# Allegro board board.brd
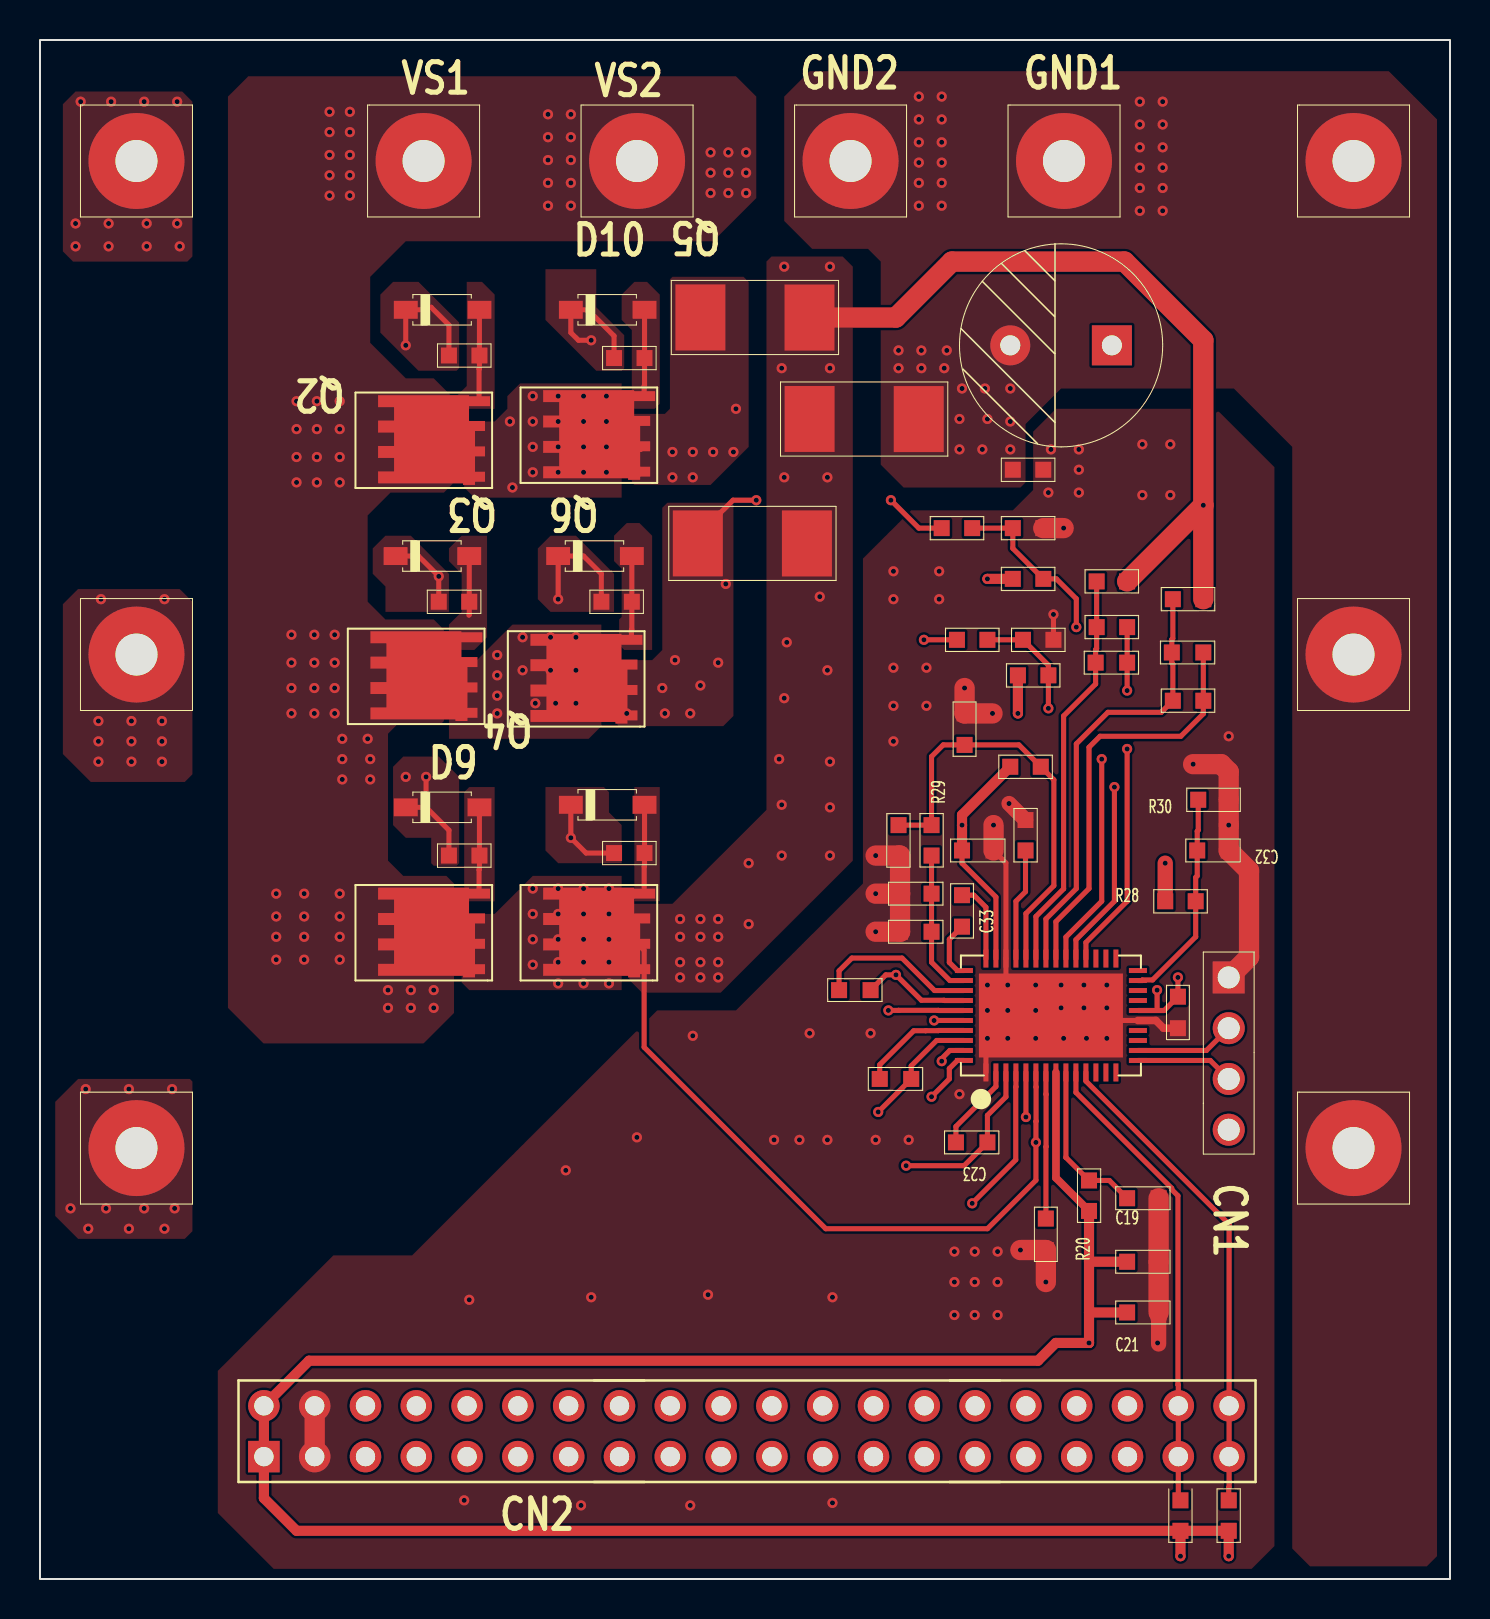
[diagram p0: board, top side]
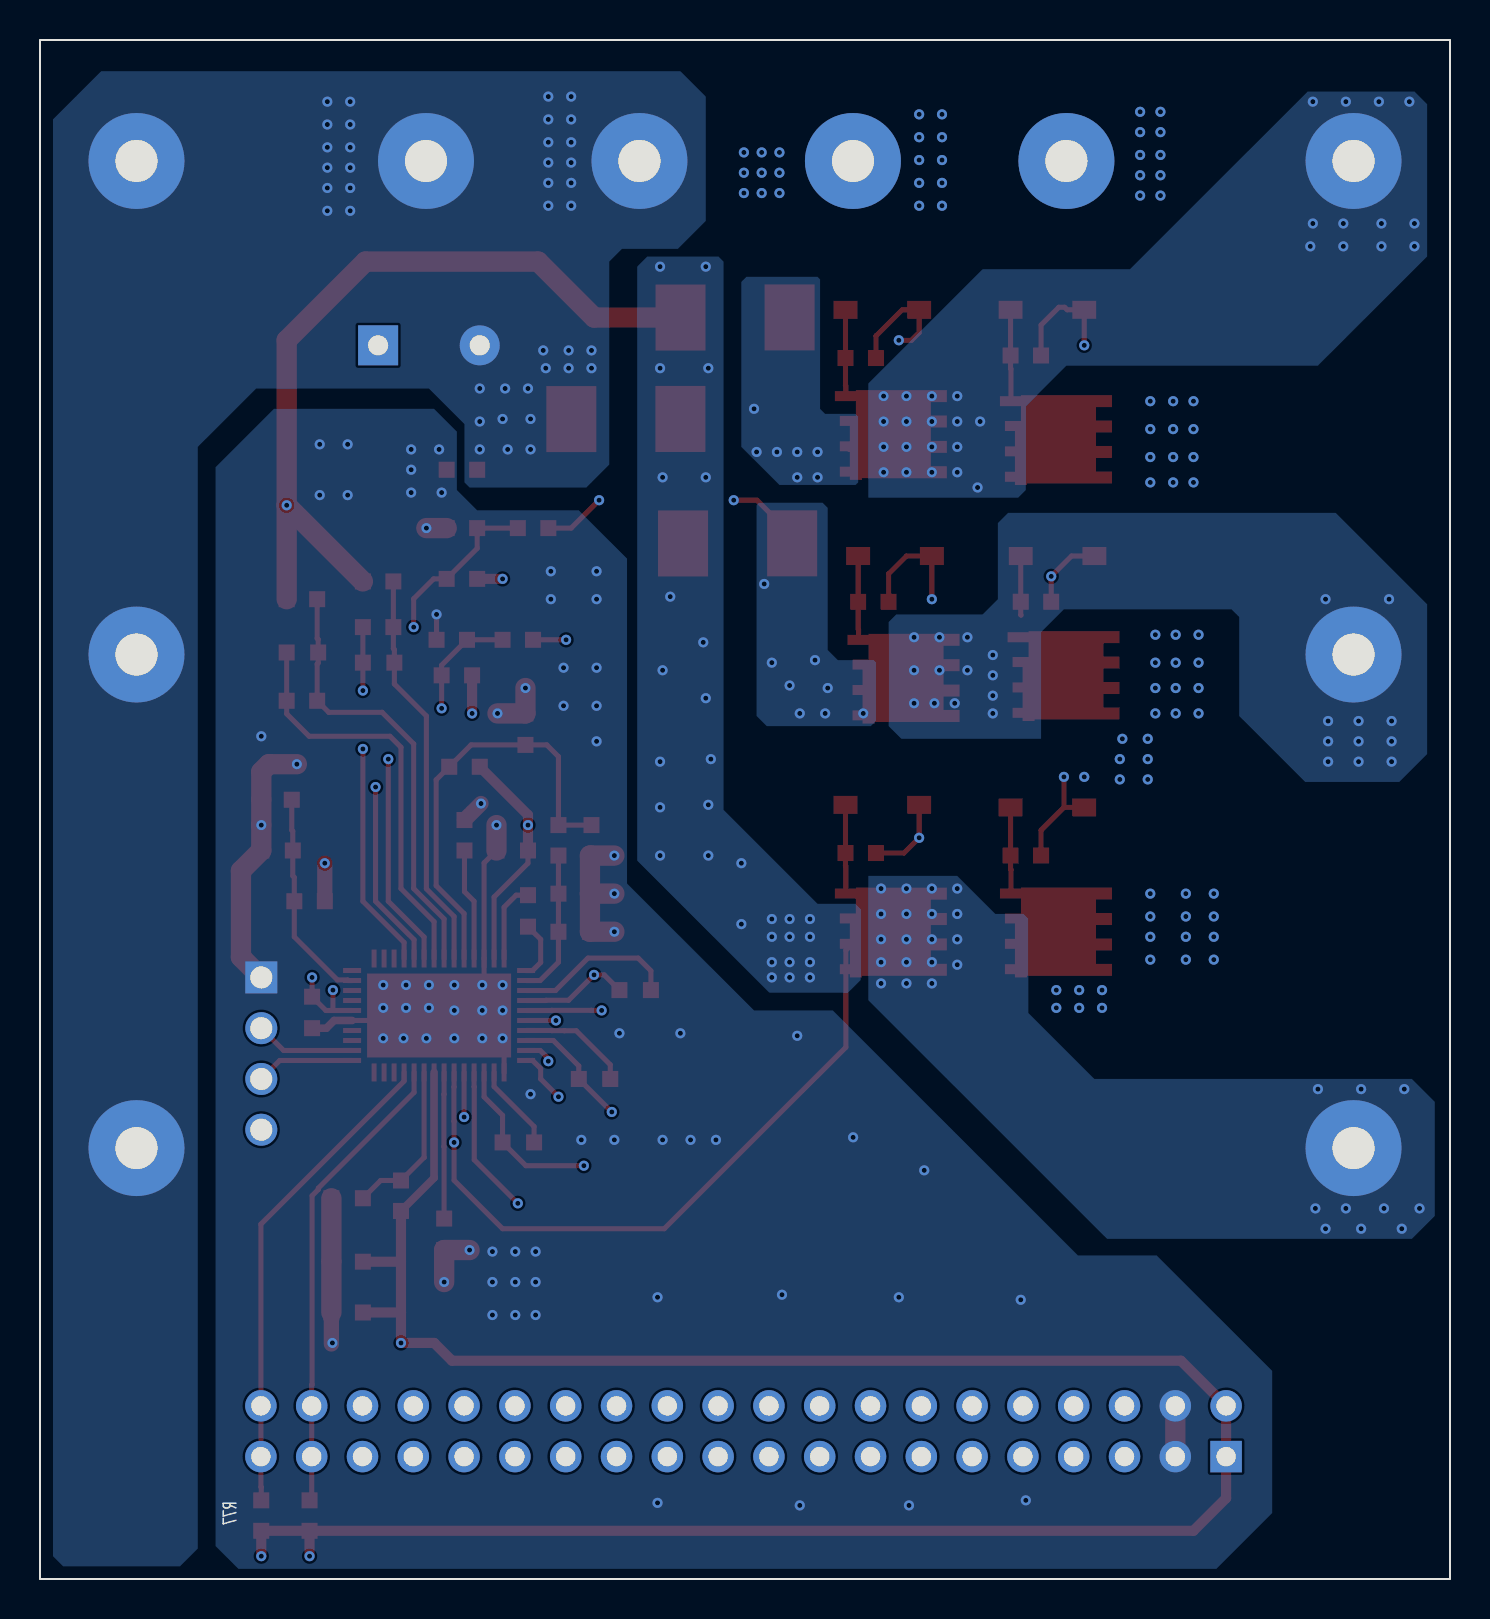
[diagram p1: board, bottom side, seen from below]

Outline 70.5 x 77 mm; copper layers: TOP, LAYER1, LAYER2, BOTTOM. Coordinates in mm from the lower left corner of the outline.
Outline path: rectangle 0,0 70.5,77

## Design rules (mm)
constraint set DEFAULT: min track width 0.127
net group N03788: nets N03788 N03879
net group N03886: nets N03886 N04171
net group IU: nets N05859 N05869 OP1- OP1O OP2- OP2O
net group OUT1: nets N03454
net group OUT2: nets N03434
net group OUT3: nets N03083

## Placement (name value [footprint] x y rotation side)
C19  0.1uF  [C0603]  54.36 19.05 0 top
C20  0.1uF  [C0603]  54.36 15.88 0 top
C21  10uF  [C0603]  54.36 13.34 0 top
C22  1uF  [C0603]  50.29 18.03 270 top
C23  0.47uF  [C0603]  47.37 21.84 180 top
C25  0.1uF  [C0603]  56.9 27.56 90 top
C30  0.47uF  [C0603]  43.56 25.02 180 top
C31  0.47uF  [C0603]  41.53 29.46 180 top
C32  0.1uF  [C0603]  59.44 36.45 180 top
C33  0.47uF  [C0603]  46.1 32.64 90 top
C34  10uF  [C0603]  44.58 32.38 180 top
C35  0.1uF  [C0603]  44.58 34.29 180 top
C36  0.1uF  [C0603]  46.1 36.45 0 top
C38  0.47uF  [C0603]  46.23 43.31 270 top
C45  0.01uF  [C0603]  54.36 45.85 180 top
C47  0.01uF  [C0603]  58.17 46.35 180 top
C48  330uF/35V  [CAP_ELECT_DIP_OD10_P5]  53.59 61.72 180 top
CN1  17.0017_4PIN_2.54mm  [CONN_DIP_4PIN_2_54MM]  59.44 30.1 270 top
CN2  17.0163_2X20_90D_female  [CONN_DIP_2X20PIN_2_54MM]  11.19 6.12 0 top
D7  200V;0.2A  [DIODES_SOD_123]  21.97 63.5 0 top
D8  200V;0.2A  [DIODES_SOD_123]  21.46 51.18 0 top
D9  200V;0.2A  [DIODES_SOD_123]  21.97 38.61 0 top
D10  200V;0.2A  [DIODES_SOD_123]  30.23 63.5 0 top
D11  200V;0.2A  [DIODES_SOD_123]  29.59 51.18 0 top
D12  200V;0.2A  [DIODES_SOD_123]  30.23 38.73 0 top
GND1  2.0mm_Male  [CONN_2_1MM_5_6MM]  51.2 70.95 0 top
GND2  2.0mm_Male  [CONN_2_1MM_5_6MM]  40.53 70.95 0 top
Q2  100V;90A  [MOS_TDSON8]  19.18 57.02 180 top
Q3  100V;90A  [MOS_TDSON8]  18.8 45.21 180 top
Q4  100V;90A  [MOS_TDSON8]  19.18 32.38 180 top
Q5  100V;90A  [MOS_TDSON8]  27.43 57.28 180 top
Q6  100V;90A  [MOS_TDSON8]  26.8 45.09 180 top
Q7  100V;90A  [MOS_TDSON8]  27.43 32.38 180 top
R20  10k  [R0603]  52.45 18.41 90 top
R28  120k  [R0603]  56.26 33.91 0 top
R29  100k  [R0603]  44.58 36.2 90 top
R30  10k  [R0603]  57.91 38.99 0 top
R31  15k  [R0603]  49.28 36.45 90 top
R33  NC  [R0603]  48.51 40.64 0 top
R36  NC  [R0603]  42.93 37.72 270 top
R43  47k  [R0603]  48.9 45.21 0 top
R44  47k  [R0603]  49.15 46.99 0 top
R45  1k  [R0603]  45.85 46.99 0 top
R47  1k  [R0603]  54.36 49.91 180 top
R51  51  [R0603]  20.45 61.21 0 top
R52  51  [R0603]  19.94 48.9 0 top
R53  51  [R0603]  20.45 36.2 0 top
R54  24k  [R0603]  54.36 47.62 180 top
R55  51  [R0603]  28.7 61.09 0 top
R56  51  [R0603]  28.07 48.9 0 top
R57  51  [R0603]  28.7 36.32 0 top
R58  47k  [R0603]  48.64 50.04 0 top
R59  47k  [R0603]  48.64 52.58 0 top
R60  0.002  [R2512]  33.02 63.12 0 top
R61  0.002  [R2512]  32.89 51.82 0 top
R62  1k  [R0603]  45.09 52.58 0 top
R64  1k  [R0603]  58.17 49.02 180 top
R65  0.005  [R2512]  38.48 58.04 0 top
R66  24k  [R0603]  58.17 43.94 180 top
R76  10k  [R0603]  57.02 3.94 270 top
R77  10k  [R0603]  59.44 3.94 270 top
R79  0  [R0603]  48.64 55.5 0 top
U1  MPF66280  [QFN48_6X9MM]  50.55 28.19 90 top
UNK1  2.0mm_Male  [CONN_2_1MM_5_6MM]  4.82 70.95 0 top
UNK2  2.0mm_Male  [CONN_2_1MM_5_6MM]  65.68 70.95 0 top
UNK3  2.0mm_Male  [CONN_2_1MM_5_6MM]  4.82 46.25 0 top
UNK4  2.0mm_Male  [CONN_2_1MM_5_6MM]  65.68 46.25 0 top
UNK5  2.0mm_Male  [CONN_2_1MM_5_6MM]  4.82 21.56 0 top
UNK6  2.0mm_Male  [CONN_2_1MM_5_6MM]  65.68 21.56 0 top
VS1  2.0mm_Male  [CONN_2_1MM_5_6MM]  19.18 70.95 0 top
VS2  2.0mm_Male  [CONN_2_1MM_5_6MM]  29.85 70.95 0 top

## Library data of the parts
C19-C23 C30 C31 C33-C36 C45 C47 = CAP;16V;X7R;0603
C25 C32 C38 = CAP;10V;X7R;0603
C48 = ELECT CAP;330uF/35V;DIP10X12
CN1 = 17.0017_4PIN_2.54mm
CN2 = 17.0163_2X20_90D_female
D7-D12 = Diode;200V;0.2A;SOD-123
GND1 GND2 UNK1-UNK6 VS1 VS2 = 17.0025_2.0mm_Male
Q2-Q7 = NMOS;100V;7;42nc;90A;TDSON-8
R20 R28-R31 R33 R36 R43-R45 R47 R51-R59 R62 R64 R66 R76 R77 R79 = RES;1%;0603
R60 R61 R65 = RES;1%;2512
U1 = IC;MPF66280_QFN48

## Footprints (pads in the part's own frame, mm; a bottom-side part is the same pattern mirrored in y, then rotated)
C0603
  rect 0.8x0.8 smd: 1(0,0) 2(1.575,0)
CAP_ELECT_DIP_OD10_P5
  rect 2x2 hole 1: 1(0,0)
  round 1.999 hole 1.001: 2(5.08,0)
CONN_2_1MM_5_6MM
  round 4.8 hole 2.1: 1(0,0)
CONN_DIP_2X20PIN_2_54MM
  rect 1.575x1.575 hole 0.965: 1(0,0)
  round 1.575 hole 0.965: 2(0,2.54) 3(2.54,0) 4(2.54,2.54) 5(5.08,0) 6(5.08,2.54) 7(7.62,0) 8(7.62,2.54) 9(10.16,0) 10(10.16,2.54) 11(12.7,0) 12(12.7,2.54) 13(15.24,0) 14(15.24,2.54) 15(17.78,0) 16(17.78,2.54) 17(20.32,0) 18(20.32,2.54) 19(22.86,0) 20(22.86,2.54) 21(25.4,0) 22(25.4,2.54) 23(27.94,0) 24(27.94,2.54) 25(30.48,0) 26(30.48,2.54) 27(33.02,0) 28(33.02,2.54) 29(35.56,0) 30(35.56,2.54) 31(38.1,0) 32(38.1,2.54) 33(40.64,0) 34(40.64,2.54) 35(43.18,0) 36(43.18,2.54) 37(45.72,0) 38(45.72,2.54) 39(48.26,0) 40(48.26,2.54)
CONN_DIP_4PIN_2_54MM
  rect 1.6x1.6 hole 1.1: 1(0,0)
  round 1.6 hole 1.1: 2(2.54,0) 3(5.08,0) 4(7.62,0)
DIODES_SOD_123
  rect 1.194x0.9 smd: 1(0,0) 2(-3.683,0)
MOS_TDSON8
  rect 1.1x0.5 smd: 1(-2.775,-1.905)
  custom 0.275x0.275 smd: 2(-2.525,0.685)
  custom 1.102x1.102 smd: 3(0,0)
QFN48_6X9MM
  rect 0.9x0.25 smd: 1(-2.85,3.25) 2(-2.85,2.75) 3(-2.85,2.25) 4(-2.85,1.75) 5(-2.85,1.25) 6(-2.85,0.75) 7(-2.85,0.25) 8(-2.85,-0.25) 9(-2.85,-0.75) 10(-2.85,-1.25) 11(-2.85,-1.75) 12(-2.85,-2.25) 13(-2.85,-2.75) 14(-2.85,-3.25) 25(2.85,-3.25) 26(2.85,-2.75) 27(2.85,-2.25) 28(2.85,-1.75) 29(2.85,-1.25) 30(2.85,-0.75) 31(2.85,-0.25) 32(2.85,0.25) 33(2.85,0.75) 34(2.85,1.25) 35(2.85,1.75) 36(2.85,2.25) 37(2.85,2.75) 38(2.85,3.25)
  rect 0.25x0.9 smd: 15(-2.25,-4.35) 16(-1.75,-4.35) 17(-1.25,-4.35) 18(-0.75,-4.35) 19(-0.25,-4.35) 20(0.25,-4.35) 21(0.75,-4.35) 22(1.25,-4.35) 23(1.75,-4.35) 24(2.25,-4.35) 39(2.25,4.35) 40(1.75,4.35) 41(1.25,4.35) 42(0.75,4.35) 43(0.25,4.35) 44(-0.25,4.35) 45(-0.75,4.35) 46(-1.25,4.35) 47(-1.75,4.35) 48(-2.25,4.35)
  rect 4.2x7.2 smd: 49(0,0)
R0603
  rect 0.8x0.8 smd: 1(0,0) 2(1.524,0)
R2512
  rect 2.5x3.302 smd: 1(0,0) 2(5.454,-0.006)

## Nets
GND: C19.2 C20.2 C21.2 C22.2 C25.1 C32.1 C34.2 C35.2 C36.2 C38.1 C48.2 CN1.1 CN2.3 CN2.4 GND1.1 GND2.1 R30.2 R31.2 R36.2 R44.2 R59.2 R65.2 R79.1 R79.2 U1.1 U1.19 U1.36 U1.49 UNK2.1 UNK4.1 UNK6.1
VIN: C36.1 C48.1 Q2.3 Q3.3 Q4.3 R28.1 R33.1 U1.37 VS1.1 VS2.1
+5: C20.1 C21.1 C25.2 CN1.4 CN2.1 CN2.2 R20.1 R43.1 R58.1 R76.2 R77.2 U1.8 U1.20
GHA: D7.2(\NN_PIN_2\) R51.1 U1.43
GHB: D8.2(\NN_PIN_2\) R52.1 U1.47
GHC: D9.2(\NN_PIN_2\) R53.1 U1.4
GLA: D10.2(\NN_PIN_2\) R55.1 U1.44
GLB: D11.2(\NN_PIN_2\) R56.1 U1.48
GLC: D12.2(\NN_PIN_2\) R57.1 U1.5
IU: Q5.2(\S\) R45.1 R60.1
IV: Q6.2(\S\) R61.1 R62.1
LSS: Q7.2(\S\) R47.1 R60.2 R61.2 R64.1 R65.1 U1.6
OP1-: C45.2 R47.2 R54.2 U1.33
OP1O: C45.1 R54.1 U1.28
OP2-: C47.2 R64.2 R66.2 U1.32
OP2O: C47.1 R66.1 U1.31
OUT1: C31.1 Q2.2(\S\) Q5.3 U1.42 UNK1.1
OUT2: C30.1 Q3.2(\S\) Q6.3 U1.46 UNK3.1
OUT3: C23.1 Q4.2(\S\) Q7.3 U1.3 UNK5.1
SCK: CN1.3 U1.15
SCL: CN2.37 CN2.38 R76.1 U1.10
SDA: CN2.39 CN2.40 R77.1 U1.11
SWD: CN1.2 U1.16
N00471: C32.2 R28.2 R30.1 U1.23
N02896: C19.1 R20.2 U1.9
N02916: C22.1 U1.7
N03083: C23.2 U1.2
N03434: C30.2 U1.45
N03454: C31.2 U1.41
N03788: C33.2 U1.38
N03879: C33.1 U1.39
N03886: C34.1 C35.1 R29.1 U1.40
N04171: C38.2 R29.2 R33.2 R36.1 U1.34
N04189: R31.1 U1.35
N05859: R58.2 R59.1 R62.2 U1.30
N05869: R43.2 R44.1 R45.2 U1.29
N16532: D7.1 Q2.1 R51.2
N16541: D10.1 Q5.1 R55.2
N16550: D11.1 Q6.1 R56.2
N16559: D12.1 Q7.1 R57.2
N16568: D8.1 Q3.1 R52.2
N16577: D9.1 Q4.1 R53.2

Pads without a net: CN2 5 6 7 8 9 10 11 12 13 14 15 16 17 18 19 20 21 22 23 24 25 26 27 28 29 30 31 32 33 34 35 36; U1 12 13 14 17 18 21 22 24 25 26 27

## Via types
v1: diameter 0.508, hole 0.254, TOP to BOTTOM, 359 vias

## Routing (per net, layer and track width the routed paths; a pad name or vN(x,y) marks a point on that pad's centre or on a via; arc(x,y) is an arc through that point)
GND: length 56
  TOP w0.127: U1.49 50.8,27.94
  TOP w0.254: v1(47.37,27.05) 47.37,26.29 47.3,26.21 U1.1 ; v1(50.67,48.26) R44.2 ; C36.2 48.3,35.83 U1.36 48.3,29.81 v1(48.39,29.72) ; 50.8,27.94 U1.19
  TOP w0.381: U1.19 55.79,27.94 56.18,27.56 C25.1
  TOP w0.762: v1(48.45,38.8) R31.2 ; C21.2 55.93,11.76
  TOP w1.016: C21.2 C20.2 C19.2 ; v1(47.68,37.72) C36.2 ; v1(47.62,43.31) C38.1 v1(46.23,44.58) ; C35.2 C34.2 v1(41.78,32.38) ; C35.2 v1(41.78,34.29) ; C35.2 43,36.2 R36.2 v1(41.78,36.2) ; CN2.3 CN2.4 ; v1(57.66,40.77) 59.05,40.77 59.44,40.39 R30.2 v1(59.44,37.72) C32.1 60.45,35.43 60.45,31.11 CN1.1 ; v1(50.29,14.86) C22.2 v1(49.02,16.46) ; R59.2 v1(51.18,52.58)
  vias: v1(21.21,3.94) v1(21.46,13.97) v1(26.29,20.45) v1(27.05,3.68) v1(27.56,14.1) v1(29.84,22.1) v1(32.51,3.68) v1(32.64,27.18) v1(33.4,14.22) v1(36.7,21.97) v1(37.97,21.97) v1(38.48,27.3) v1(39.37,21.97) v1(39.62,14.1) v1(39.62,3.81) v1(41.53,27.3) v1(41.78,21.97) v1(42.67,50.42) v1(42.67,49.02) v1(42.67,45.59) v1(42.67,43.69) v1(42.67,41.91) v1(42.93,61.47) v1(42.93,60.58) v1(43.43,21.97) v1(43.94,74.17) v1(43.94,73.03) v1(43.94,71.88) v1(43.94,70.87) v1(43.94,69.85) v1(43.94,68.71) v1(44.07,61.47) v1(44.07,60.58) v1(44.32,45.59) v1(44.32,43.69) v1(44.96,50.42) v1(44.96,49.02) v1(45.09,74.17) v1(45.09,73.03) v1(45.09,71.88) v1(45.09,70.87) v1(45.09,69.85) v1(45.09,68.71) v1(45.21,60.58) v1(45.34,61.47) v1(45.72,16.38) v1(45.72,14.86) v1(45.72,13.21) v1(45.97,58.04) v1(45.97,56.52) v1(45.97,24.26) v1(46.1,59.56) v1(46.74,16.38) v1(46.74,14.86) v1(46.74,13.21) v1(47.12,56.52) v1(47.24,59.56) v1(47.37,58.04) v1(47.37,29.72) v1(47.37,28.45) v1(47.88,16.38) v1(47.88,14.86) v1(47.88,13.21) v1(48.39,28.45) v1(48.39,27.05) v1(48.51,59.56) v1(48.51,57.91) v1(48.51,56.52) v1(49.78,29.72) v1(49.78,28.45) v1(49.78,27.05) v1(50.42,54.36) v1(50.55,56.52) v1(51.05,29.72) v1(51.05,28.57) v1(51.18,27.05) v1(51.94,56.52) v1(51.94,55.5) v1(51.94,54.36) v1(52.2,29.72) v1(52.2,28.57) v1(52.32,27.05) v1(53.34,29.72) v1(53.34,28.57) v1(53.34,27.05) v1(54.99,73.91) v1(54.99,72.77) v1(54.99,71.63) v1(54.99,70.61) v1(54.99,69.6) v1(54.99,68.45) v1(55.12,56.77) v1(55.12,54.23) v1(55.88,11.81) v1(56.13,73.91) v1(56.13,72.77) v1(56.13,71.63) v1(56.13,70.61) v1(56.13,69.6) v1(56.13,68.45) v1(56.52,56.77) v1(56.52,54.23) v1(59.44,42.16)
VIN: length 77.6
  TOP w0.254: C36.1 46.1,35.81 47.8,34.12 U1.37
  TOP w0.508: C36.1 v1(46.1,37.72) 46.1,38.23 R33.1
  TOP w0.762: v1(56.26,35.81) R28.1
  LAYER1 w0.508: 51.22,40.85 51.22,44.87 53.59,47.24 C48.1
  LAYER1 w0.762: v1(56.26,35.81) 51.22,40.85 46.86,40.85 46.1,40.09 v1(46.1,37.72)
  LAYER1 w1.016: C48.1 48.26,67.06 33.74,67.06 29.83,70.97
  vias: v1(11.81,34.29) v1(11.81,33.15) v1(11.81,32.13) v1(11.81,30.99) v1(12.57,47.24) v1(12.57,45.85) v1(12.57,44.58) v1(12.57,43.31) v1(12.83,58.93) v1(12.83,57.53) v1(12.83,56.13) v1(12.83,54.86) v1(13.21,34.29) v1(13.21,33.15) v1(13.21,32.13) v1(13.21,30.99) v1(13.72,47.24) v1(13.72,45.85) v1(13.72,44.58) v1(13.72,43.31) v1(13.84,58.93) v1(13.84,57.53) v1(13.84,56.13) v1(13.84,54.86) v1(14.48,73.41) v1(14.48,72.39) v1(14.48,71.25) v1(14.48,70.23) v1(14.48,69.22) v1(14.73,47.24) v1(14.73,45.85) v1(14.73,44.58) v1(14.73,43.31) v1(14.99,58.93) v1(14.99,57.53) v1(14.99,56.13) v1(14.99,54.86) v1(14.99,34.29) v1(14.99,33.15) v1(14.99,32.13) v1(14.99,30.99) v1(15.11,42.04) v1(15.11,41.02) v1(15.11,40.01) v1(15.49,73.41) v1(15.49,72.39) v1(15.49,71.25) v1(15.49,70.23) v1(15.49,69.22) v1(16.38,42.04) v1(16.51,41.02) v1(16.51,40.01) v1(17.4,29.46) v1(17.4,28.57) v1(18.54,29.46) v1(18.54,28.57) v1(19.68,29.46) v1(19.68,28.57) v1(25.4,73.28) v1(25.4,72.14) v1(25.4,70.99) v1(25.4,69.85) v1(25.4,68.71) v1(26.54,73.28) v1(26.54,72.14) v1(26.54,70.99) v1(26.54,69.85) v1(26.54,68.71) v1(33.53,71.37) v1(33.53,70.36) v1(33.53,69.34) v1(34.42,71.37) v1(34.42,70.36) v1(34.42,69.34) v1(35.31,71.37) v1(35.31,70.36) v1(35.31,69.34)
+5: length 166.7
  TOP w0.254: 55.85,28.44 v1(55.85,29.46) ; 55.85,28.44 U1.20 ; 55.85,28.44 56.21,28.44 C25.2 v1(56.9,30.1)
  TOP w0.381: U1.8 50.8,20.07 R20.1
  TOP w0.508: R76.2 12.83,2.41 11.19,4.05 CN2.1 CN2.2 13.45,10.92 49.9,10.92 50.79,11.81 v1(52.45,11.81) 52.45,13.34 ; R76.2 v1(57.02,1.14) ; R76.2 R77.2 v1(59.44,1.14) ; 52.45,15.88 R20.1 ; 52.45,15.88 52.45,13.34 ; 52.45,15.88 C20.1 ; 52.45,13.34 C21.1 ; R43.1 v1(48.9,43.31) ; R58.1 v1(47.37,50.04)
  LAYER1 w0.508: v1(52.45,11.81) 51.56,10.92 13.45,10.92 CN2.2
GHA: length 57.8
  TOP w0.254: v1(42.42,28.45) 42.93,28.45 42.93,28.45 44.91,28.45 44.92,28.44 U1.43 ; R51.1 20.45,62.74 19.56,63.63 19.27,63.63 19.14,63.5 D7.2 v1(18.29,61.72)
  LAYER2 w0.254: v1(18.29,61.72) 20.95,59.05 20.95,54.48 22.61,52.83 27.69,52.83 38.23,42.29 38.23,29.46 39.24,28.45 v1(42.42,28.45)
GHB: length 49.6
  TOP w0.254: v1(45.09,25.91) 45.09,26.04 45.49,26.44 U1.47 ; R52.1 v1(19.94,50.16) 18.92,51.18 D8.2
  LAYER2 w0.254: v1(45.09,25.91) 44.73,25.55 38.21,25.55 36.2,27.56 36.2,42.67 29.08,49.78 20.32,49.78 v1(19.94,50.16)
GHC: length 61.5
  TOP w0.254: D9.2 19.3,38.61 ; 19.3,38.61 20.45,37.47 R53.1 ; 19.3,38.61 v1(19.3,40.13) ; U1.4 48.8,24.62 48.79,24.61 48.79,20.97 v1(46.61,18.8)
  LAYER2 w0.254: v1(18.29,40.13) 14.22,36.07 14.22,30.35 25.78,18.8 v1(46.61,18.8)
GLA: length 49.1
  TOP w0.254: R55.1 28.7,62.19 27.39,63.5 D10.2 26.54,62.36 26.92,61.98 v1(27.56,61.98) ; U1.44 v1(44.7,27.94)
  LAYER2 w0.254: v1(27.56,61.98) 28.19,61.98 29.34,60.83 29.34,53.72 43.69,39.37 43.69,28.96 v1(44.7,27.94)
GLB: length 47.3
  TOP w0.254: v1(25.91,49.02) D11.2 27.18,51.18 28.07,50.29 R56.1 ; U1.48 45.87,25.94 45.47,25.54 45.47,25.02 v1(44.58,24.13)
  LAYER2 w0.254: v1(25.91,49.02) 28.96,45.97 30.73,45.97 34.67,42.04 34.67,25.65 36.2,24.13 v1(44.58,24.13)
GLC: length 51.6
  TOP w0.254: R57.1 27.3,36.32 v1(26.54,37.08) D12.2 ; v1(49.3,23.11) U1.5
  LAYER2 w0.254: v1(49.3,23.11) 49.3,22.5 46.74,19.94 29.84,19.94 20.95,28.83 20.95,33.15 24.89,37.08 v1(26.54,37.08)
IU: length 18
  TOP w0.254: Q5.2 30.04,56.51 ; R45.1 v1(44.2,46.99)
  LAYER2 w0.254: v1(44.2,46.99) 39.24,46.99 35.18,51.05 35.18,55.88 v1(34.67,56.39)
  vias: v1(31.62,56.39) v1(31.62,55.12) v1(32.64,56.39) v1(32.64,55.12) v1(33.66,56.39) v1(34.8,58.55)
IV: length 13.9
  TOP w0.254: R61.1 32.89,52.22 34.65,53.98 v1(35.81,53.98) ; v1(42.55,53.98) 43.94,52.58 R62.1
  LAYER2 w0.254: v1(42.55,53.98) v1(35.81,53.98)
  vias: v1(29.34,43.31) v1(31.11,44.58) v1(31.24,43.31) v1(31.75,45.97) v1(32.51,43.31) v1(33.02,44.7) v1(33.91,45.85) v1(34.29,49.78)
LSS: length 122.1
  TOP w0.254: U1.6 49.8,24.62 49.8,24.61 49.8,22.9 49.8,22.9 v1(49.8,21.84) 49.8,19.95 47.37,17.53 39.29,17.53 30.21,26.61 30.21,31.45 Q7.2
  TOP w1.016: R64.1 v1(58.17,53.72) ; v1(58.17,53.72) R47.1 ; v1(58.17,53.72) 58.17,61.98 54.23,65.91 45.59,65.91 42.79,63.11 R60.2
  LAYER2 w0.254: v1(58.17,53.72) 59.69,53.72 61.09,52.32 61.09,21.59 60.2,20.7 50.94,20.7 v1(49.8,21.84)
  vias: v1(32,33.02) v1(32,32.13) v1(32,30.86) v1(32,30.1) v1(33.02,33.02) v1(33.02,32.13) v1(33.02,30.86) v1(33.02,30.1) v1(33.91,33.02) v1(33.91,32.13) v1(33.91,30.86) v1(33.91,30.1) v1(35.43,35.81) v1(35.43,32.77) v1(36.96,41.02) v1(37.08,60.58) v1(37.08,38.73) v1(37.08,36.2) v1(37.21,65.66) v1(37.21,55.12) v1(37.21,44.07) v1(37.34,46.86) v1(38.99,49.15) v1(39.37,55.12) v1(39.37,45.47) v1(39.5,65.66) v1(39.5,60.58) v1(39.5,40.89) v1(39.5,38.61) v1(39.5,36.2)
OP1-: length 20.1
  TOP w0.254: R47.2 R54.2 52.83,46.55 52.78,46.5 C45.2 52.78,44.78 51.18,43.18 51.18,34.53 49.8,33.15 U1.33
OP1O: length 17.6
  TOP w0.254: U1.28 52.3,31.85 54.36,33.91 v1(54.36,41.53) ; v1(54.36,44.45) C45.1 R54.1 54.23,47.75
  LAYER2 w0.254: v1(54.36,41.53) v1(54.36,44.45)
OP2-: length 22.2
  TOP w0.254: R64.2 56.64,47.06 56.59,47.01 C47.2 56.59,45.83 56.64,45.78 R66.2 56.06,43.36 53.4,43.36 51.82,41.78 51.82,34.54 50.3,33.02 U1.32
OP2O: length 20.9
  TOP w0.254: U1.31 50.8,32.89 52.45,34.54 52.45,41.61 53,42.16 57.04,42.16 58.17,43.29 R66.1 C47.1 58.17,46.48
OUT1: length 40.3
  TOP w0.127: Q5.3 27.18,57.28
  TOP w0.254: 26.38,56.23 Q5.3 ; U1.42 45.21,28.94 45.2,28.96 44.07,28.96 v1(42.8,30.23) 42.29,30.23 C31.1
  LAYER2 w0.254: v1(42.8,30.23) 42.16,30.86 38.86,30.86 38.61,31.11 38.61,43.43 28.32,53.72 v1(28.32,55.37)
  vias: v1(1.78,67.82) v1(1.78,66.67) v1(2.03,73.91) v1(3.43,67.82) v1(3.43,66.67) v1(3.56,73.91) v1(5.21,73.91) v1(5.33,67.82) v1(5.33,66.67) v1(6.86,73.91) v1(6.86,67.82) v1(6.99,66.67) v1(23.5,57.91) v1(23.62,54.61) v1(24.64,59.18) v1(24.64,57.91) v1(24.64,56.64) v1(24.64,55.37) v1(25.91,59.18) v1(25.91,57.91) v1(25.91,56.64) v1(25.91,55.37) v1(27.18,59.18) v1(27.18,57.91) v1(27.18,56.64) v1(27.18,55.37) v1(28.32,59.18) v1(28.32,57.91) v1(28.32,56.64)
OUT2: length 40.6
  TOP w0.254: v1(26.8,43.81) 27.16,43.46 27.16,43.2 ; U1.46 44.83,26.94 43.56,25.67 C30.1 v1(41.91,23.37) ; Q6.3 v1(26.8,45.47)
  LAYER2 w0.254: v1(26.8,43.81) 27.66,42.95 27.66,42.69 29.46,40.89 29.46,26.16 32.26,23.37 v1(41.91,23.37) ; 25.48,46.48 24.89,46.48 24.64,46.74
  vias: v1(2.92,42.93) v1(2.92,41.91) v1(2.92,40.89) v1(3.05,49.02) v1(4.57,42.93) v1(4.57,41.91) v1(4.57,40.89) v1(6.1,42.93) v1(6.1,41.91) v1(6.1,40.89) v1(6.22,49.02) v1(22.86,46.23) v1(22.86,45.21) v1(22.86,44.2) v1(22.86,43.31) v1(24.13,47.12) v1(24.13,45.47) v1(24.77,43.81) v1(25.53,47.12) v1(25.53,45.47) v1(25.78,43.81) v1(26.8,47.12)
OUT3: length 31.2
  TOP w0.254: 27.18,32.64 Q7.3 26.31,32.38 ; U1.3 48.3,24.12 47.37,23.2 C23.1 46.21,20.68 v1(43.31,20.68)
  LAYER2 w0.254: v1(28.45,29.8) 28.45,25.27 33.04,20.68 v1(43.31,20.68)
  vias: v1(1.52,18.54) v1(2.29,24.51) v1(2.41,17.53) v1(3.3,18.54) v1(4.45,24.51) v1(4.45,17.53) v1(5.21,18.54) v1(6.22,17.53) v1(6.6,24.51) v1(6.73,18.54) v1(24.64,34.54) v1(24.64,33.27) v1(24.64,32) v1(24.64,30.73) v1(25.91,34.54) v1(25.91,33.27) v1(25.91,32) v1(25.91,30.86) v1(25.91,29.8) v1(27.18,34.54) v1(27.18,33.27) v1(27.18,32) v1(27.18,30.86) v1(27.18,29.8) v1(28.45,34.54) v1(28.45,33.27) v1(28.45,32) v1(28.45,30.86)
SCK: length 4.9
  TOP w0.254: CN1.3 58.51,25.94 U1.15
SCL: length 23.6
  TOP w0.254: U1.10 51.8,24.34 56.58,19.56 56.58,19.49 56.9,19.18 56.9,9.72 56.91,9.71 CN2.38 CN2.37 56.91,4.05 R76.1
SDA: length 24.4
  TOP w0.254: R77.1 59.44,4.59 59.45,4.61 CN2.39 CN2.40 59.45,17.75 52.3,24.91 U1.11
SWD: length 5
  TOP w0.254: U1.16 58.32,26.44 CN1.2
N00471: length 10.7
  TOP w0.254: U1.23 55.12,29.94 55.12,29.97 55.63,29.97 57.78,32.13 57.78,35.1 57.86,35.18 C32.2 57.86,37.41 57.91,37.47 R30.1
N02896: length 8.2
  TOP w0.254: C19.1 53.47,19.94 R20.2 51.3,21.09 ; 51.3,21.09 51.3,21.08 ; 51.3,21.09 U1.9
N02916: length 7.3
  TOP w0.254: U1.7 50.3,24.26 50.3,24.25 50.3,21.63 50.3,21.63 50.3,18.04 C22.1
N03083: length 4.3
  TOP w0.254: U1.2 47.8,24.64 45.8,22.64 C23.2
N03434: length 5.6
  TOP w0.254: U1.45 44.92,27.44 44.91,27.44 44.28,27.44 44.28,27.43 43.69,27.43 41.99,25.73 C30.2
N03454: length 8.1
  TOP w0.254: U1.41 44.72,29.44 43.1,31.07 40.59,31.07 39.95,30.43 C31.2
N03788: length 4
  TOP w0.254: U1.38 47.3,33.61 46.69,34.21 C33.2
N03879: length 3
  TOP w0.254: C33.1 45.47,32 45.47,30.85 45.87,30.44 U1.39
N03886: length 7.3
  TOP w0.254: R29.1 C35.1 C34.1 44.58,30.86 45.49,29.94 U1.40
N04171: length 21.7
  TOP w0.254: R36.1 R29.2 44.58,41.15 45.16,41.73 C38.2 48.95,41.73 R33.2 50.69,39.99 50.69,34.69 49.3,33.29 U1.34
N04189: length 5.6
  TOP w0.254: U1.35 48.8,33.91 49.28,34.39 R31.1
N05859: length 26.5
  TOP w0.254: v1(51.82,47.62) 51.82,49.04 50.82,50.04 R58.2 48.64,51.56 R59.1 R62.2 ; v1(53.09,41.02) 53.09,33.91 51.3,32.12 U1.30
  LAYER2 w0.254: v1(53.09,41.02) 53.09,45.34 51.82,46.61 v1(51.82,47.62)
N05869: length 20.4
  TOP w0.254: v1(53.72,39.62) 53.72,33.91 51.8,31.98 U1.29 ; v1(50.42,43.56) R43.2 50.42,45.72 R44.1 R45.2
  LAYER2 w0.254: v1(50.42,43.56) 50.42,43.05 50.55,42.93 50.55,42.8 v1(53.72,39.62)
N16532: length 4.3
  TOP w0.254: 21.95,59.18 21.95,60.54 21.97,60.56 R51.2 D7.1
N16541: length 4.3
  TOP w0.254: D10.1 R55.2 30.23,59.71 30.21,59.69 Q5.1
N16550: length 4.2
  TOP w0.254: Q6.1 29.57,47.49 29.59,47.51 R56.2 D11.1
N16559: length 4.5
  TOP w0.254: Q7.1 30.21,35.65 30.23,35.67 R57.2 D12.1
N16568: length 3
  TOP w0.254: D8.1 R52.2 21.46,48.24 21.44,48.22
N16577: length 4.3
  TOP w0.254: Q4.1 21.95,35.48 21.97,35.5 R53.2 D9.1

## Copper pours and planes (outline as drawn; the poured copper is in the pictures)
GND on TOP, BOTTOM, LAYER2: 67.44,75.44 38.48,75.44 37.21,74.17 37.21,67.94 38.61,66.55 41.4,66.55 42.04,65.91 42.04,55.75 43.18,54.61 49.02,54.61 49.28,54.86 49.28,57.78 51.05,59.56 59.69,59.56 62.61,56.64 62.61,1.52 63.5,0.64 69.34,0.64 69.85,1.14 69.85,73.03
GND on TOP, BOTTOM, LAYER2: 49.66,57.4 49.66,54.48 48.64,53.47 43.56,53.47 41.15,51.05 41.15,34.8 34.8,28.45 30.86,28.45 18.61,16.19 14.67,16.19 8.89,10.41 8.89,3.3 11.68,0.51 60.58,0.51 61.72,1.65 61.72,55.63 58.8,58.55 50.8,58.55
VIN on TOP, LAYER2: 11.18,26.8 19.18,26.8 20.7,28.32 20.7,34.8 20.32,35.18 18.16,35.18 17.4,35.94 17.4,42.29 17.91,42.8 20.07,42.8 20.19,42.93 20.19,47.5 19.68,48.01 17.27,48.01 16.38,48.9 16.38,53.21 17.53,54.36 20.19,54.36 20.7,54.86 20.7,59.05 19.68,60.07 18.29,60.07 16.51,61.85 16.51,65.15 18.29,66.93 33.66,66.93 35.81,69.09 35.81,74.17 34.8,75.18 10.41,75.18 9.4,74.17 9.4,28.57
VIN on LAYER1: 11.18,26.8 19.18,26.8 20.7,28.32 20.7,34.8 20.32,35.18 18.16,35.18 17.4,35.94 17.4,42.29 17.91,42.8 20.07,42.8 20.19,42.93 20.19,47.5 19.68,48.01 17.27,48.01 16.38,48.9 16.38,53.21 17.53,54.36 20.19,54.36 20.7,54.86 20.7,59.05 19.68,60.07 18.29,60.07 16.51,61.85 16.51,65.15 18.29,66.93 33.15,66.93 33.53,66.55 47.24,66.55 51.56,62.23 51.56,60.2 52.2,59.56 57.53,59.56 59.31,61.34 59.31,74.93 59.05,75.18 10.41,75.18 9.4,74.17 9.4,28.57
+5 on LAYER1: 49.66,57.4 49.66,54.48 48.64,53.47 43.56,53.47 41.15,51.05 41.15,34.8 34.8,28.45 30.86,28.45 18.61,16.19 14.67,16.19 8.89,10.41 8.89,3.3 11.68,0.51 60.58,0.51 61.72,1.65 61.72,55.63 58.8,58.55 50.8,58.55
GHA on TOP: 18.92,64.9 17.65,64.9 17.02,64.26 17.02,62.36 18.92,60.45 20.83,60.45 20.95,60.58 20.95,62.87
GHB on TOP: 17.27,48.39 20.45,48.39 20.45,50.29 18.54,52.2 17.27,52.2 16.64,51.56 16.64,50.29 17.27,49.66
GHC on TOP: 19.94,41.15 18.16,41.15 17.65,40.64 17.65,37.72 18.29,37.08 19.56,37.08 19.56,35.81 19.68,35.69 20.83,35.69 20.95,35.81 20.95,40.13
GLA on TOP: 27.81,63.63 27.81,65.53 25.27,65.53 25.27,62.99 27.81,60.45 29.08,60.45 29.21,60.58 29.21,62.23
GLB on TOP: 26.8,52.2 28.7,50.29 28.7,48.39 25.53,48.39 24.89,49.02 24.89,51.56 25.53,52.2
GLC on TOP: 25.27,39.62 25.27,36.45 25.91,35.81 29.08,35.81 29.08,37.72 28.45,38.35 28.45,39.37 28.19,39.62
IU on TOP, BOTTOM, LAYER1, LAYER2: 29.72,54.74 29.59,54.86 29.59,58.17 29.72,58.29 31.24,58.29 31.5,58.55 31.5,65.02 31.62,65.15 35.18,65.15 35.43,64.9 35.43,56.64 33.53,54.74
IV on TOP, BOTTOM, LAYER1, LAYER2: 28.7,42.93 28.7,45.85 28.83,45.97 30.61,45.97 31.11,46.48 31.11,53.59 31.37,53.85 34.54,53.85 34.67,53.72 34.67,43.18 34.16,42.67 28.96,42.67
LSS on TOP, BOTTOM, LAYER1, LAYER2: 30.1,29.34 29.46,29.97 29.46,33.53 29.72,33.78 31.62,33.78 36.32,38.48 36.32,65.91 36.58,66.17 40.13,66.17 40.64,65.66 40.64,35.94 34.04,29.34
OUT1 on TOP, LAYER1: 1.78,74.42 1.14,73.79 1.14,66.42 1.65,65.91 7.37,65.91 7.62,66.17 7.62,73.91 7.11,74.42
OUT1 on TOP, LAYER1, LAYER2: 21.34,57.91 22.73,57.91 23.37,58.55 23.37,59.18 24,59.82 29.08,59.82 29.08,54.1 21.72,54.1 21.21,54.61 21.21,57.78
OUT1 on BOTTOM: 1.78,74.42 1.14,73.79 1.14,66.17 6.6,60.71 19.18,60.71 21.21,58.67 21.21,54.48 21.59,54.1 29.08,54.1 29.08,59.82 23.37,65.53 16,65.53 7.11,74.42
OUT2 on TOP, LAYER1: 1.91,49.53 1.14,48.77 1.14,41.27 2.54,39.88 7.24,39.88 7.62,40.26 7.62,48.9 6.99,49.53
OUT2 on TOP, LAYER1, LAYER2: 20.45,42.04 20.45,45.85 21.72,45.85 23.62,47.75 28.07,47.75 28.07,42.67 27.43,42.04
OUT2 on BOTTOM: 1.14,41.27 2.54,39.88 7.24,39.88 10.54,43.18 10.54,48.13 10.92,48.51 19.3,48.51 20.45,47.37 20.45,42.04 27.43,42.04 28.07,42.67 28.07,47.88 27.69,48.26 23.37,48.26 22.61,49.02 22.61,52.83 22.1,53.34 5.71,53.34 1.14,48.77
OUT3 on TOP, LAYER1: 1.91,25.02 0.76,23.88 0.76,18.16 1.91,17.02 7.24,17.02 7.62,17.4 7.62,24.89 7.49,25.02
OUT3 on TOP, LAYER1, LAYER2: 21.34,33.27 22.73,33.27 24.64,35.18 29.08,35.18 29.08,29.46 21.46,29.46 21.08,29.84 21.08,33.02
OUT3 on BOTTOM: 1.91,25.02 0.76,23.88 0.76,18.16 1.91,17.02 17.14,17.02 29.08,28.96 29.08,35.18 24.64,35.18 22.73,33.27 21.34,33.27 21.08,33.02 21.08,28.32 17.78,25.02
N16532 on TOP: 22.73,58.55 22.73,64.26 22.1,64.9 21.34,64.9 21.34,59.69 20.83,59.18 20.83,58.55
N16541 on TOP: 29.72,58.55 30.73,58.55 30.99,58.8 30.99,64.26 30.35,64.9 29.72,64.9 29.08,64.26 29.08,62.99 29.59,62.48 29.59,58.67
N16550 on TOP: 30.61,46.48 30.61,52.2 29.97,52.83 29.34,52.83 28.7,52.2 28.7,50.93 29.08,50.55 29.08,48.13 28.96,48.01 28.96,46.74 29.21,46.48
N16559 on TOP: 29.72,33.91 30.99,33.91 30.99,39.62 29.72,39.62
N16568 on TOP: 20.45,47.12 20.45,47.75 21.08,48.39 21.08,50.29 20.45,50.93 20.45,51.56 21.08,52.2 22.35,52.2 22.35,47.12 21.72,46.48 21.08,46.48
N16577 on TOP: 22.73,39.62 22.73,33.91 21.34,33.91 21.21,34.04 21.21,39.37 21.46,39.62
